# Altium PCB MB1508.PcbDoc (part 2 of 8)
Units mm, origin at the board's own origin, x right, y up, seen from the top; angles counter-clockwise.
Board outline 129 x 77 mm, 4 copper layers (Top Layer, GND, POWER, Bottom Layer), stack 1.582 mm thick; 399 components, 297 nets, 1407 pads, 1316 vias.
Unrouted connection lines stored in the file: 535.
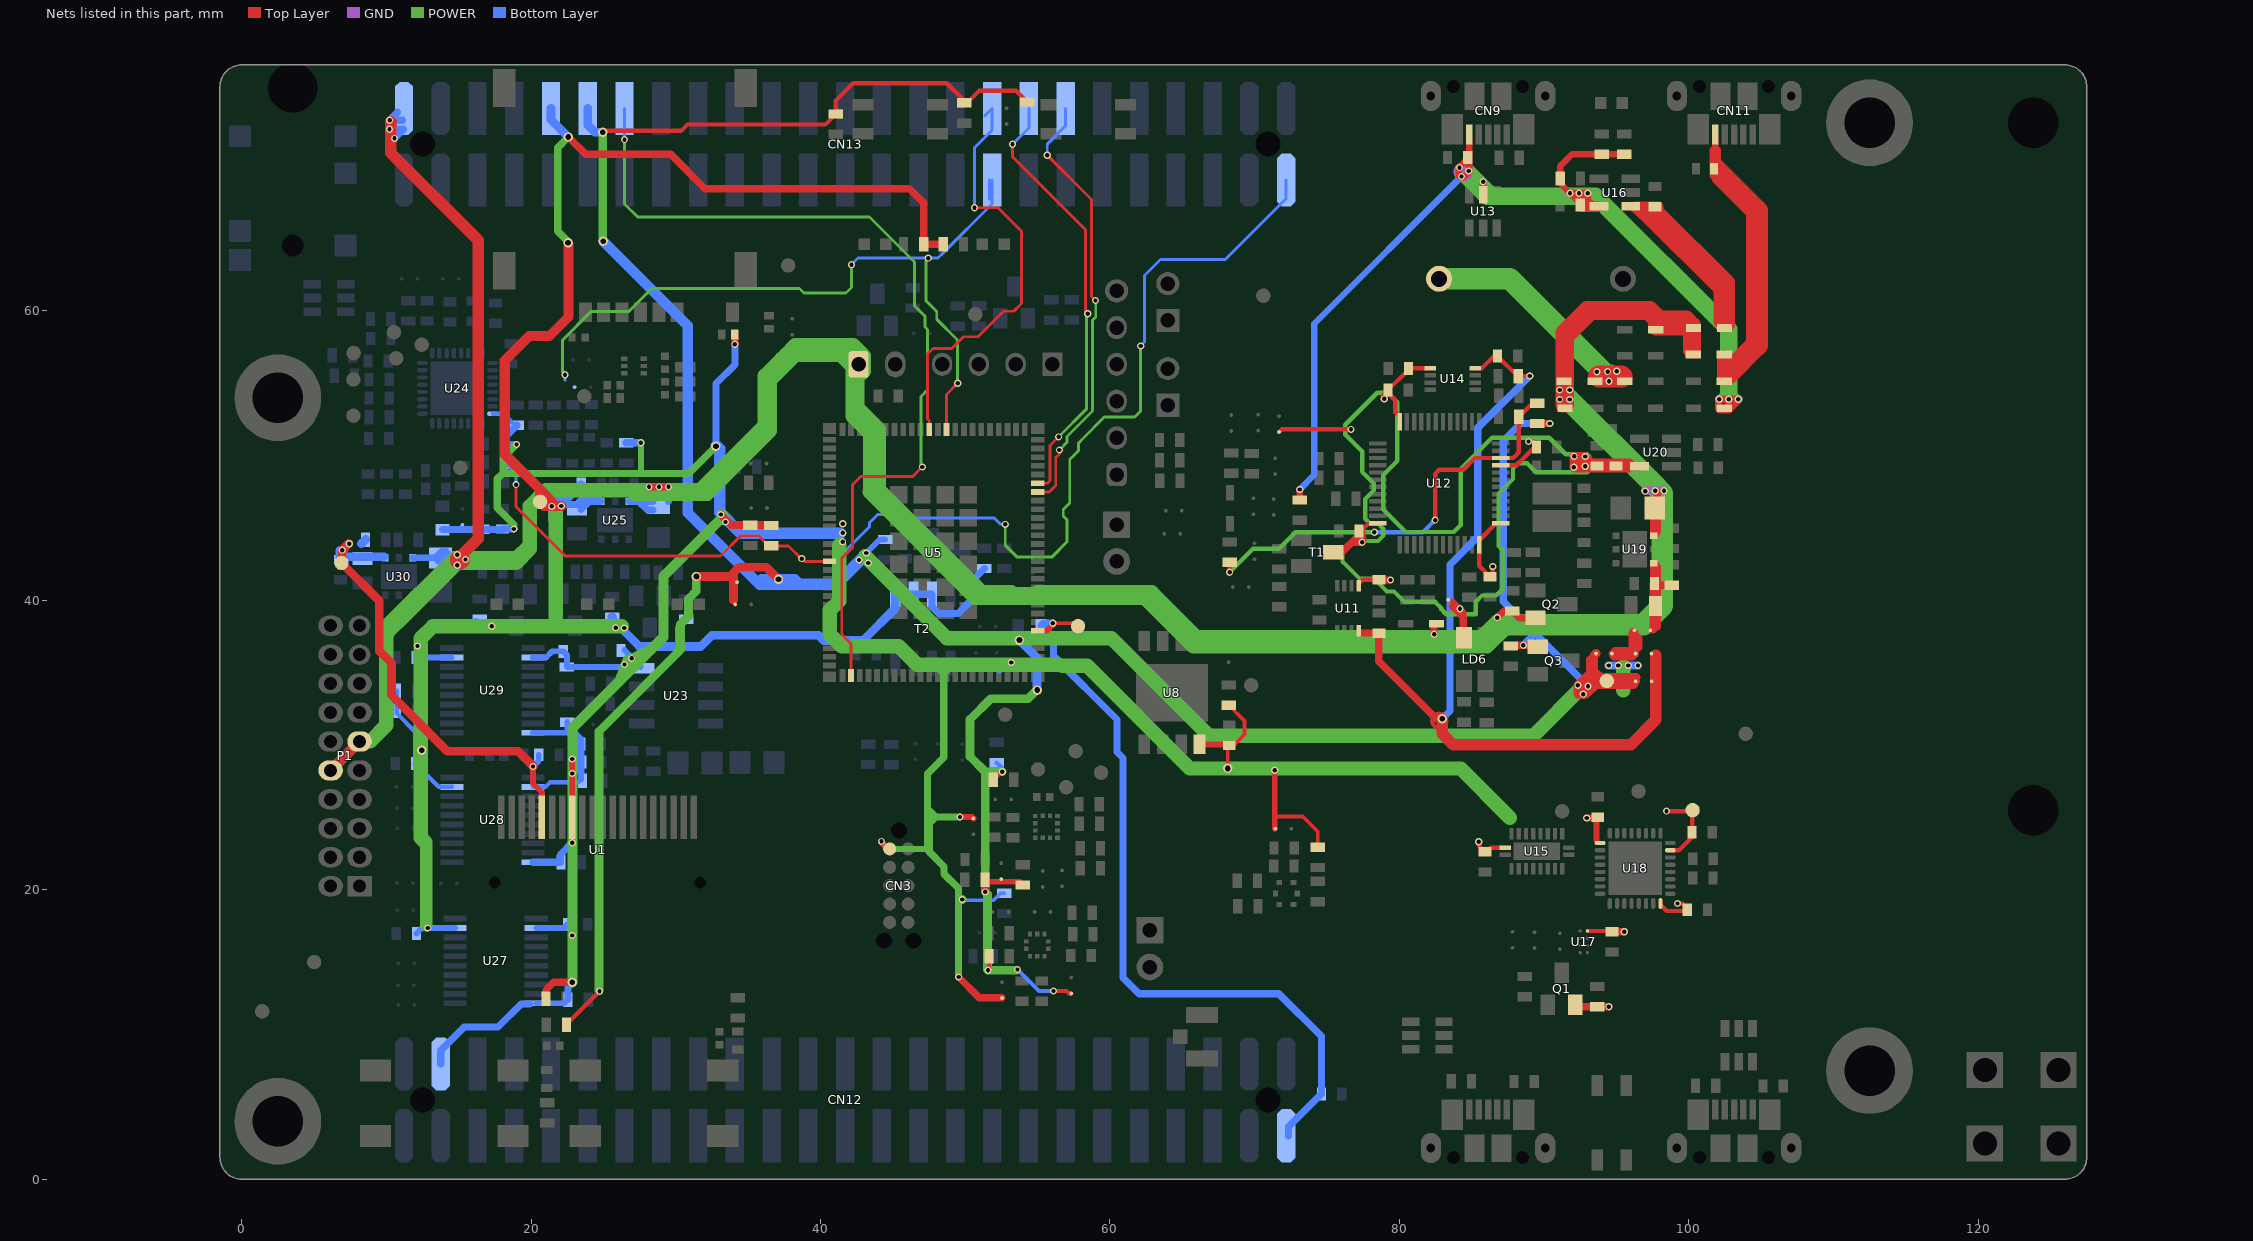
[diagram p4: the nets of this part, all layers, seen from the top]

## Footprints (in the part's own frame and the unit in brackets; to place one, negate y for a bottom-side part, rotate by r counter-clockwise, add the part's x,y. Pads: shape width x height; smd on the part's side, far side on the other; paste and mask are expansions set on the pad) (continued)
R0603 [mm]
  rect 0.64x1 smd mask+0.05: 1(-0.7,0) 2(0.7,0)
  silkscreen extent -1.05,-0.58 1.05,0.58, body extent -0.9,-0.5 0.9,0.5, height 0.56
REG_SOT23-5L [mm]
  rect 0.6x1.3 smd mask+0.05: 1(-0.95,-1.1) 2(0,-1.1) 3(0.95,-1.1) 4(0.95,1.1) 5(-0.95,1.1)
  silkscreen extent -1.6,-0.95 1.6,0.97, body extent -1.52,-1.25 1.52,1.25, height 1.1
SOLDER-BRIDGE_R0603-0R [mil]
  round 10 smd paste-393.7: 1(-19.68,0) 2(23.62,0)
  Top Layer region: -47.24,-19.69 -47.24,19.68 -15.75,19.68 3.94,0 -15.75,-19.69 -47.24,-19.69
  Top Layer region: -5.91,19.68 13.78,0 -5.91,-19.69 47.24,-19.69 47.24,19.68 -5.91,19.68
  silkscreen extent -50,-23 50,23, body extent -36,-20 36,20, height 22
STICKER_25X9 [mm] "Sticker 25mm x 9mm"
  silkscreen extent -12.5,-4.5 12.5,4.5
SWI_PANASONIC_EVQP2F02K [mm]
  rect 1.45x0.8 smd mask+0.05: 1(2.575,1) 2(2.575,-1) 3(-2.575,1) 4(-2.575,-1)
  silkscreen extent -2.4,-1.8 2.4,1.8, body extent -2.9,-1.8 2.9,1.8, height 2.7
SWI_WEALTHMETAL_TD-0341_4P_BLACK [mm]
  rect 1.52x2.16 smd mask+0.05: 1(-2.25,-4.75) 2(-2.25,4.75) 3(2.25,-4.75) 4(2.25,4.75)
  silkscreen extent -3,-3.5 3,3.5, body extent -3,-5.15 3,5.15, height 7.55
SWI_WEALTHMETAL_TD-0341_4P_BLUE [mm]
  rect 1.52x2.16 smd mask+0.05: 1(-2.25,-4.75) 2(-2.25,4.75) 3(2.25,-4.75) 4(2.25,4.75)
  silkscreen extent -3,-3.5 3,3.5, body extent -3,-5.15 3,5.15, height 7.55
TP_SMD_1MM [mm]
  round 1 smd paste-10 mask+0.05: 1(0,0)
  silkscreen extent -0.7,-0.7 0.7,0.7
预留天线 [mm]
  round 3.2 hole 3.5 unplated: 1(-6,34.5) 2(-6,-13)

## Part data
B1: library part MCD-00001, "Non-Open Push-Button 0.1A 24V BLACK", Manufacturer=WEALTHMETAL, Manufacturer_Part_Number=TD-0341
B2: library part MCD-00002, "Non-Open Push-Button 0.1A 24V", Manufacturer=WEALTHMETAL, Manufacturer_Part_Number=TD-0341
B3 B4 B5: library part MCD-00168, "EVQP2 - 4.7mm x 3.5 mm SMD Light Touch Switch", Manufacturer=PANASONIC, Manufacturer_Part_Number=EVQP2F02K
BT1: library part MCD-01623, "3xAAA ECONOMICAL PLASTIC BATTERY HOLDER", Manufacturer=KEYSTONE, Manufacturer_Part_Number=2479
C1 C6: library part MCD-00102, "Capacitor, MLCC, 100nF, 16V, X7R, 10%, 0402, T=0,5mm", Alternate_Manufacturer=MURATA, Alternate_Manufacturer_Part_Number=GCM155R71C104KA55D, Manufacturer=YAGEO, Manufacturer_Part_Number=CC0402KRX7R7BB104, Package=C0402
C2: library part MCD-00006, "Capacitor, MLCC, 100nF, 16V, X7R, 10%, 0402, T=0.5mm", Alternate_Manufacturer=MURATA, Alternate_Manufacturer_Part_Number=GCM155R71C104KA55D, Manufacturer=YAGEO, Manufacturer_Part_Number=CC0402KRX7R7BB104, Package=C0402
C3 C4 C5: library part MCD-00277, "Capacitor, MLCC, 33pF, 50V, NPO, 5%, 0402, T=0,5mm", Manufacturer=YAGEO, Manufacturer_Part_Number=CC0402JRNPO9BN330, Package=C0402
C7: library part MCD-01341, "Capacitor, MLCC, 10uF, 6V3, X5R, 20%, 0603, T=0,8mm"
C8 C10 C13 C14 C15 C16 C21 C22 C24 C29 C33 C42 C48 C49 C61 C64 C66 C68 C69 C72 C75 C87 C88 C89 C90: library part MCD-00237, "Capacitor, MLCC, 100nF, 6V3, X5R, 10%, 0603, T=0,8mm", Manufacturer=YAGEO, Manufacturer_Part_Number=CC0603KRX5R5BB104, Package=C0603
C9: library part MCD-00243, "Capacitor, MLCC, 10uF, 6V3, X5R, 10%, 0603, T=0,8mm", Manufacturer=YAGEO, Manufacturer_Part_Number=CC0603KRX5R5BB106, Package=C0603
C11 C46: library part MCD-00009, "Capacitor, MLCC, 4.7uF, 16V, X5R, 10%, 0603, T=0.8mm", Manufacturer=YAGEO, Manufacturer_Part_Number=CC0603KRX5R7BB475, Package=C0603
C12: library part MCD-00602, "Capacitor, MLCC, 220nF, 16V, 0402, X7R, 10%, T=0,5mm", Manufacturer=MURATA, Manufacturer_Part_Number=GRM155R71C223KA01J, Package=C0402
C17: library part MCD-00012, "Capacitor, MLCC, 2.2uF, 10V, X5R, 10%, 0603, T=0,8mm", Alternate_Manufacturer=KEMET, Alternate_Manufacturer_Part_Number=C0603C225K8PACTU, Manufacturer=YAGEO, Manufacturer_Part_Number=CC0603KRX5R6BB225, Package=C0603
C18: library part MCD-00638, "Capacitor, MLCC, 20pF, 50V, NPO, 5%, 0603, T=0,8mm", Manufacturer=YAGEO, Manufacturer_Part_Number=CC0603JRNPO9BN200, Package=C0603
C19 C20 C23 C25 C26 C28 C30 C31 C41 C43: library part MCD-00211, "Capacitor, MLCC, 100nF, 16V, X7R, 10%, 0603, T=0,8mm", Manufacturer=YAGEO, Manufacturer_Part_Number=CC0603KRX7R7BB104, Package=C0603
C27 C35: library part MCD-01006, "Capacitor, MLCC, 470nF, 16V, X7R, 10%, 0603, T=0.8mm", Manufacturer=YAGEO, Manufacturer_Part_Number=CC0603KRX7R7BB474, Package=C0603
C32 C45 C47 C50 C51 C57 C60 C62 C67 C73 C76 C77 C78 C79 C80 C81 C82: library part MCD-00238, "Capacitor, MLCC, 1uF, 6V3, X5R, 10%, 0603, T=0,8mm", Manufacturer=YAGEO, Manufacturer_Part_Number=CC0603KRX5R5BB105, Package=C0603
C34: library part MCD-00017, "Capacitor, MLCC, 10nF, 50V, X7R, 10%, 0603, T=0.8mm", Manufacturer=YAGEO, Manufacturer_Part_Number=CC0603KRX7R9BB103, Package=C0603
C36 C37 C56: library part MCD-00637, "Capacitor, MLCC, 10pF, 50V, NPO, 5%, 0603, T=0,8mm", Manufacturer=YAGEO, Manufacturer_Part_Number=CC0603JRNPO9BN100, Package=C0603
C38 C52 C55 C58 C84: library part MCD-00007, "Capacitor, Tantalum, 4.7uF, 16V, 10%, 4ohms, pkg Type_A (3216 metric), T=1.6mm", Manufacturer=AVX, Manufacturer_Part_Number=TAJA475K016R, Package=Type_A
C39 C70 C86: library part MCD-00014, "Capacitor, MLCC, 10uF, 25V, X5R, 10%, 0805, T=0,85mm", Manufacturer=YAGEO, Manufacturer_Part_Number=CC0805KRX5R8BB106, Package=C0805
C40 C44 C63 C74 C83 C85: library part MCD-00010, "Capacitor, MLCC, 1uF, 16V, X5R, 10%, 0603, T=0,8mm", Manufacturer=YAGEO, Manufacturer_Part_Number=CC0603KRX5R7BB105, Package=C0603
C53: library part MCD-00273, "Capacitor, MLCC, 1nF, 16V, X7R, 10%, 0603, T=0,8mm"
C54: library part MCD-01007, "Capacitor, MLCC, 10nF, 16V, X7R, 10%, 0603, T=0.8mm"
C59 C65: library part MCD-00238, "Capacitor, MLCC, 1uF, 6V3, X5R, 10%, 0603, T=0,8mm"
C71: library part MCD-00551, "Capacitor, MLCC, 2.2uF, 10V, X5R, 10%, 0603, T=0,8mm", Alternate_Manufacturer=YAGEO, Alternate_Manufacturer_Part_Number=CC0603KRX5R6BB225, Manufacturer=KEMET, Manufacturer_Part_Number=C0603C225K8PACTU, Package=C0603
CN1: library part MCD-01701, "RF Coxial Cable to uFL"
CN2: library part MCD-01699, "Socket_microsim 17.17*16.75, height 1.5mm, 6PIN"
CN3: library part MCD-00031, "Tag_Connector Header, 10x2, No legs", Manufacturer="TAG-CONNECT LLC", Manufacturer_Part_Number=TC2050-IDC-NL-FP
CN4: library part MCD-00313, "Header, 4x1, 2.54mm, VR, TH, Height 6mm/3mm", Alternate_Manufacturer=LIANYI, Alternate_Manufacturer_Part_Number=313104S1411160, Manufacturer=JIUBABA, Manufacturer_Part_Number=PHFS25-11-04-G0B115-T-1
CN5: library part MCD-00316, "Header, 6x1, 2.54mm, VR, TH, Height 6mm/3mm", Alternate_Manufacturer=LIANYI, Alternate_Manufacturer_Part_Number=313106S1411160, Manufacturer=JIUBABA, Manufacturer_Part_Number=PHFS25-11-06-G0B115-T-1
CN6: library part MCD-01583, "U.FL RF connector"
CN7: library part MCD-01581, "Header 2x1, 2.54mm, VR, TH, height 5.84mm/5.08 mm, height total 13.46 mm", Manufacturer=SAMTEC, Manufacturer_Part_Number=TSW-102-08-G-S
CN8 CN9 CN10 CN11: library part MCD-01698, "Micro-USB B Receptacle without Flange, Top Mount, Surface Mount, Lead-Free"
CN12 CN13: library part MCD-01931, "Header, 25x2, 2,54mm, VR, TH, Height 5.84mm/2.54mm, with alignment Pin"
CN14: library part MCD-01695, "Connector Jack socket Stereo 3.5mm, SMT", Manufacturer=TAIYI
D1 D2 D3 D4 D5 D6 D7 D8 D9 D10 D11 D12: library part MCD-00034, Manufacturer=STMICROELECTRONICS
H1 H2 H3 H4: library part MCD-00035, "POSITION HOLE C6D3R5"
HW8: library part MCD-00235, "Sticker to mention board reference + serial number", Manufacturer=n/a
HW9: library part MCD-00547, "Sticker to mention board CPN code", Manufacturer=n/a
JP1 JP2: library part MCD-00683, "Header, 2x1, 2,54mm, VR, TH, Height 5.84mm/2.54mm - Shunt Fitted by default", Alternate_Manufacturer=LIANYI, Alternate_Manufacturer_Part_Number=313102S111116, Manufacturer=SAMTEC, Manufacturer_Part_Number=TSW-102-07-x-S
JP3 JP4: library part MCD-00045, "Header, 2x1, 2,54mm, VR, TH, Height 5.84mm/2.54mm", Alternate_Manufacturer="JIUBABA; LIANYI", Alternate_Manufacturer_Part_Number=313102S111116;313102S111116, Manufacturer=SAMTEC, Manufacturer_Part_Number=TSW-102-07-x-S
L1: library part MCD-00047, "SMD Chip ferrite bead, 600R@100MHz +/-25%, 350mA, 500mohm DC, 0603, T=0.8mm", Manufacturer=TAI-TECH, Manufacturer_Part_Number=FCM1608KF-601T03
L2: library part MCD-01724, "Ferrite bead, 1000R @ 100MHz,  600mA, 350mOhm, 0603", Manufacturer=MURATA, Manufacturer_Part_Number=BLM18HE102SN1D
LD1 LD4 LD5: library part MCD-00320, "LED, Green, 0603", Manufacturer=EVERLIGHT, Manufacturer_Part_Number=19-213SY6C/S530-E2/TR8LED, Package="LED 0603"
LD2: library part MCD-00322, "LED, Red, 0603", Manufacturer=EVERLIGHT, Manufacturer_Part_Number=19-217/R6C-AL1M2VY/3T, Package="LED 0603"
LD3: library part MCD-00585, "LED Blue, 0603 SMD, Forward Voltage Min=2,8V, Max=3,8V", Alternate_Manufacturer=EVERLIGHT, Alternate_Manufacturer_Part_Number=19-217-BHC-ZL1M2RY-3T-V4, Manufacturer="OSRAM OPTO SEMICONDUCTORS", Manufacturer_Part_Number="LB Q39G-L2OO-35-1", Package="LED 0603"
LD6: library part MCD-00051, "LED Bicolor", Alternate_Manufacturer=EVERLUCK, Alternate_Manufacturer_Part_Number=LE-RGW35280, Manufacturer="AVAGO TECHNOLOGIES", Manufacturer_Part_Number=HSMF-A201-A00J1
LD7: library part MCD-00049, "LED, Red, 0603", Manufacturer=EVERLIGHT, Manufacturer_Part_Number=19-213-R6C-AP1Q2B/3T, Package="LED 0603"
P1: library part MCD-00309, "Socket 10x2, 2.00mm, RA, TH, Height 6.35mm/2.29mm", Alternate_Manufacturer=JIUBABA;CONNECT, Alternate_Manufacturer_Part_Number=FH200020C-12300;CNT-F200-2*10-GD-635/2.3, Manufacturer=SAMTEC, Manufacturer_Part_Number=SQT-110-01-F-D-RA
Q1 Q2: library part MCD-01494, "MOSFET, P-Channel , Vds: -20V, Id: -2.4A, Vgs(th): -1.5V, Vgs(max): +/-8V, Rdson:100mohm@Vgs=-1.8V", Alternate_Manufacturer="ON SEMICONDUCTOR", Alternate_Manufacturer_Part_Number=FDN304PZ, Manufacturer_Part_Number=FDN304P, Package=SOT23-3
Q3 Q6: library part MCD-01163, "MOSFET, N-Channel , Vds: 20V, Id: 2A, Vgs(th): 1.5V, Vgs(max): +/-8V, Rdson:120mohm@Vgs=1.8V, Qg=6.3nC", Manufacturer=FAIRCHILD, Manufacturer_Part_Number=FDN327N, Package=SOT-23-3
Q4 Q5 Q7 Q8 Q9 T1: library part MCD-00073, "NPN Bipolar Transistor", Alternate_Manufacturer="ON SEMICONDUCTOR", Alternate_Manufacturer_Part_Number="MMBT2222LT1G / MMBT2222ALT1G / MMBT2222ALT3G", Manufacturer_Part_Number=BSR14, Package=SOT23
R1 R3 R10 R11 R13 R18 R20 R21 R22 R30 R39 R40 R44 R53 R56 R60 R61 R65 R72 R74 R80 R82 R84 R97 R103 R105 R106 R122: library part MCD-00220, "Resistor,10K,0603,1%,1/10W", Manufacturer=YAGEO, Manufacturer_Part_Number=RC0603FR-0710KL, Package=R0603
R2 R37 R41 R42: library part MCD-00224, "Resistor,100R,0603,1%,1/10W", Manufacturer=YAGEO, Manufacturer_Part_Number=RC0603FR-07100RL, Package=R0603
R4 R8 R9: library part MCD-00285, "Resistor,15K,0402,5%,1/16W", Manufacturer=YAGEO, Manufacturer_Part_Number=RC0402JR-0715KL, Package=R0402
R5 R6 R7: library part MCD-00286, "Resistor,18R,0402,5%,1/16W", Manufacturer=YAGEO, Manufacturer_Part_Number=RC0402JR-0718RL, Package=R0402
R12 R75 R81 R83: library part MCD-00190, "Resistor,22R,0603,1%,1/10W", Manufacturer=YAGEO, Manufacturer_Part_Number=RC0603FR-0722RL, Package=R0603
R14 R16 R46 R48 R51 R54 R58 R59 R66 R67 R71 R73 R77 R79 R94 R107 R116: library part MCD-00223, "Resistor,100K,0603,1%,1/10W", Manufacturer=YAGEO, Manufacturer_Part_Number=RC0603FR-07100KL, Package=R0603
R15 R17 R88 R98 R118: library part MCD-00225, "Resistor,510R,0603,1%,1/10W", Manufacturer=YAGEO, Manufacturer_Part_Number=RC0603FR-07510RL, Package=R0603
R19 R23 R24 R25 R26 R27 R28 R35 R38 R45 R78 R87 R91 R93 R96 R99 R100 R110 R111 R123: library part MCD-00056, "Resistor,0R,0603,5%,1/10W", Manufacturer=YAGEO, Manufacturer_Part_Number=RC0603JR-070RL, Package=R0603
R29 R31 R32 R33 R34: library part MCD-00066, "Resistor,22R,0603,1%,1/10W", Manufacturer=YAGEO, Manufacturer_Part_Number=RC0603FR-0722RL, Package=R0603
R36: library part MCD-00221, "Resistor,36K,0603,1%,1/10W", Manufacturer=YAGEO, Manufacturer_Part_Number=RC0603FR-0736KL, Package=R0603
R43: library part MCD-00217, "Resistor,1K5,0603,1%,1/10W", Manufacturer=YAGEO, Manufacturer_Part_Number=RC0603FR-071K5L, Package=R0603
R47: library part MCD-00218, "Resistor,2K7,0603,1%,1/10W", Manufacturer=YAGEO, Manufacturer_Part_Number=RC0603FR-072K7L, Package=R0603
R49 R55 R62 R108 R109 R120 R121: library part MCD-00219, "Resistor,4K7,0603,1%,1/10W", Manufacturer=YAGEO, Manufacturer_Part_Number=RC0603FR-074K7L, Package=R0603
R50 R52: library part MCD-00197, "Resistor,330R,0603,1%,1/10W", Manufacturer=YAGEO, Manufacturer_Part_Number=RC0603FR-07330RL, Package=R0603
R57 R63 R70 R86 R89 R90 R101 R113: library part MCD-00222, "Resistor,47K,0603,1%,1/10W", Manufacturer=YAGEO, Manufacturer_Part_Number=RC0603FR-0747KL, Package=R0603
R64 R76: library part MCD-00070, "Resistor,1K,0603,1%,1/10W", Manufacturer=YAGEO, Manufacturer_Part_Number=RC0603FR-071KL, Package=R0603
R68: library part MCD-00478, "Resistor,43K,0603,1%,1/10W", Manufacturer=YAGEO, Manufacturer_Part_Number=RC0603FR-0743KL, Package=R0603
R69 R104 R119: library part MCD-01149, "Resistor,20K5,0603,1%,1/10W", Manufacturer=YAGEO, Manufacturer_Part_Number=RC0603FR-0720K5L, Package=R0603
R85 R102: library part MCD-00056, "Resistor,0R,0603,5%,1/10W"
R92: library part MCD-00506, "Resistor,620K,0603,1%,1/10W", Manufacturer=YAGEO, Manufacturer_Part_Number=RC0603FR-07620KL, Package=R0603
R95: library part MCD-00244, "Resistor,11K8,0603,1%,1/10W", Manufacturer=YAGEO, Manufacturer_Part_Number=RC0603FR-0711K8L, Package=R0603
R112 R114 R115: library part MCD-01723, "Resistor,2K15,0603,1%,1/10W", Manufacturer=YAGEO, Manufacturer_Part_Number=RC0603FR-072K15L, Package=R0603
R117: library part MCD-01155, "Resistor,10K2,0603,1%,1/10W", Manufacturer=YAGEO, Manufacturer_Part_Number=RC0603FR-0710K2L, Package=R0603
SB1 SB2 SB3 SB4 SB5 SB7 SB8 SB9 SB10 SB11 SB12 SB14 SB15 SB16 SB17 SB18 SB19 SB20 SB22 SB27 SB30 SB34 SB36 SB37 SB38 SB40 SB42 SB43 SB44 SB45 SB46 SB47 SB48 SB49 SB50 SB53 SB57 SB58 SB60 SB61: library part MCD-00071, "Solder Bridge ON", Manufacturer=YAGEO, Manufacturer_Part_Number=RC0603JR-070RL, Package=SB0603
SB6 SB13 SB21 SB23 SB24 SB25 SB26 SB28 SB29 SB31 SB32 SB33 SB35 SB39 SB41 SB51 SB52 SB54 SB55 SB56 SB59: library part MCD-00072, "Solder Bridge OFF", Manufacturer=YAGEO, Manufacturer_Part_Number=RC0603JR-070RL, Package=SB0603
T2: library part MCD-00572, "Power MOSFET - P-channel 30V - 0.045 OHM - 5A SO-8 - STripFET", Manufacturer=STMICROELECTRONICS
TP1 TP2 TP3 TP4 TP5 TP6 TP7 TP8 TP9 TP10 TP11 TP12 TP13 TP14 TP15 TP16 TP17 TP18 TP19 TP20 TP21 TP22 TP23 TP24 TP25: library part MCD-00074, "Test Point 1mm", Manufacturer=n/a
U1: library part MCD-01511, "128*64 20-pin OLED display driver SSD1306BZ Parallel or SPI interface", Manufacturer=RITDISPLAY, Manufacturer_Part_Number=9OL9935701000
U2 U4 U21: library part MCD-00251, "High power transient voltage suppressor, 7V breakdown", Manufacturer=STMICROELECTRONICS, Manufacturer_Part_Number=ESDA7P60-1U1M
U3: library part MCD-01696, "ESD protection", Manufacturer=WILLSEMI, Package=SOT-563
U5: library part MCD-01700, "NBIoT Module", Manufacturer=Murata, Manufacturer_Part_Number=TYPE-1SE
U6: library part MCD-01702, "High-performance MEMS nano pressure sensor:260-1260 hPa absolute digital output barometer", Manufacturer=STMICROELECTRONICS, Package=HLGA-10L
U7: library part MCD-00709, "3D accelerometer and 3D magnetometer", Manufacturer=STMICROELECTRONICS
U8: library part MCD-01749, "512Mb, 1.8V Multiple I/O Serial Flash Memory", Manufacturer=Micron, Package=W-PDFN-8
U9 U13 U22: library part MCD-00163, "Very low capacitance ESD protection", Manufacturer=STMICROELECTRONICS
U10: library part MCD-01447, "Capacitive digital sensor for relative humidity and temperature", Manufacturer=STMICROELECTRONICS, Package=HLGA-6L
U11 U14: library part MCD-00264, "Dual bit dual supply bus transceiver", Manufacturer="TEXAS INSTRUMENTS"
U12: library part MCD-00085, "Medium-density performance line ARM-based 32-bit MCU with 128KB Flash", Manufacturer=STMICROELECTRONICS
U15: library part MCD-01620, "Octal buffer/line driver with 5 V tolerant inputs/outputs; 3-state", Manufacturer=Nexperia, Manufacturer_Part_Number=74LVC541ABQ,115, Package=DHVQFN20
U16: library part MCD-00083, "Enhanced single channel power switches with active low enable pin", Alternate_Manufacturer="TEXAS INSTRUMENTS", Alternate_Manufacturer_Part_Number=TPS2041C, Manufacturer=STMICROELECTRONICS
U17: library part MCD-01624, "Dual-Channel 10-Ω SPST Analog Switch", Manufacturer="TEXAS INSTRUMENTS", Package=DSBGA
U18: library part MCD-01622, "USB-Serial Dual Channel (UART/I2C/SPI) Bridge"
U19 U25 U30: library part MCD-00581, "LDO Linear Voltage Regulator IC Positive Adjustable 1 Output Adjustable 1.3A 6-DFN (3x3)", Manufacturer=STMICROELECTRONICS, Package="DFN6 (3x3)"
U20: library part MCD-00086, "Ultra low drop-low noise BiCMOS voltage, regulators low ESR capacitors compatible", Manufacturer=STMICROELECTRONICS
U23: library part MCD-00293, "I2C memory", Manufacturer=STMICROELECTRONICS
U24: library part MCD-01621, "Ultra-Low Power Stereo Audio Codec"
U26: library part MCD-00247, "Quad Bidir ESD protection", Manufacturer=STMICROELECTRONICS
U27 U28 U29: library part MCD-00289, "8bits_bidirectionnal level shifter, Delay 312ns/1V8", Manufacturer="TEXAS INSTRUMENTS"
X1: library part MCD-00092, "Crystal 8MHz, 8pF, +-20ppm, 500ohms max,  SMD", Manufacturer=NDK, Manufacturer_Part_Number="NX3225GD 8MHz EXS00A-CG04874"
X2: library part MCD-01836, "Oscillator 26Mhz, +-2ppm, Vcc:1.8V typ (1.7V min), square wave: [0.1Vcc;0.9Vcc]", Manufacturer=TXC, Package="2016 size"

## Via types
v1: diameter 0.5, hole 0.3, Top Layer to Bottom Layer, tented both sides, 1301 vias
v2: diameter 0.65, hole 0.4, Top Layer to Bottom Layer, tented both sides, 14 vias
v3: diameter 0.5/0.5/0.5/0.5 (per signal layer), hole 0.3, Top Layer to Bottom Layer, tented both sides, 1 vias

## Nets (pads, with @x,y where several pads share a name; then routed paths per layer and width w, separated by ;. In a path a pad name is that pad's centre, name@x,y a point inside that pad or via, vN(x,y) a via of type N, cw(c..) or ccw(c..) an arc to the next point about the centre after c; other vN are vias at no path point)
1V8: C15.2 C27.1 C33.2 C35.1 C45.1 C46.1 C59.1 C61.1 C63.1 C64.1 C68.1 C69.1 C72.2 C73.1 CN3.1 CN12.48 L2.2 Q1.2 R3.1 R8.2 R10.2 R13.2 R40.1 R44.2 R65.1 R72.2 R85.2 R89.2 R103.1 R105.1 R106.1 R108.1 R109.1 SB7.2 SB12.2 SB27.1 SB33.2 SB34.2 SB36.2 SB39.2 SB51.1 TP24.1 U1.8 U8.8 U15.20 U17.A2 U18.1 U18.16 U18.23 U23.8 U24.32 U27.2 U27.10 U28.2 U28.10 U29.2 U29.10 | length 299.6
  Top Layer w0.254: v2(68.143,28.382) 68.143,29.868 C15.2@68.25,29.976 ; R40.1@68.212,32.753 69.298,31.667 69.298,30.72 C15.2@68.554,29.976 ; SB27.1@71.387,24.272 SB27.1@71.437,24.222 ; 71.387,25.06 73.33,25.06 74.358,24.033 R44.2@74.358,22.93 ; U17.A2@92.999,17.15 C35.1@94.401,17.15 ; U18.1@93.663,23.277 93.544,23.395 93.544,24.854 93.676,24.723 93.718,24.681 93.718,23.229 U18.1@93.872,23.229
  Top Layer w0.3: v1@85.497,23.318 v1(85.486,23.318) 85.486,23.067 C27.1@85.929,22.624 ; C27.1@86.114,22.702 86.32,22.908 U15.20@87.306,22.908 ; U18.16@98.047,19.054 98.047,18.96 98.48,18.527 99.696,18.527 99.897,18.728 99.572,19.053 v1(99.219,19.053) ; v1(98.459,25.433) 99.987,25.433 100.239,25.182 C46.1@100.239,24.049 ; U18.23@98.722,22.729 99.318,22.729 100.237,23.648 100.237,24.475
  Top Layer w0.4: v1(22.85,23.241) U1.8@22.85,24.999 v1(22.85,28.037) v1(22.85,29.038) ; v1(44.218,23.341) 44.218,23.266 44.66,22.824 CN3.1@44.781,22.824 ; v1(49.644,25.031) 50.464,25.031 SB7.2@50.563,24.932 ; U8.8@66.191,30.039 68.187,30.039 C15.2@68.25,29.976 ; SB27.1@71.387,24.222 71.387,24.272 71.387,25.06 v1(71.387,28.26)
  Top Layer w0.5: R3.1@21.025,12.476 21.025,13.081 21.554,13.61 v2(22.842,13.61) ; R8.2@34.082,58.358 34.085,58.354 v1(34.085,57.697) ; v1(49.543,13.971) 50.978,12.536 SB12.2@52.546,12.536 ; Q1.2@92.158,12.062 92.31,11.91 R65.1@93.68,11.91 v1(94.48,11.91) ; v1(92.947,24.957) C33.2@93.647,24.957 ; C33.2@93.544,24.854 C33.2@93.647,24.957 ; C33.2@93.709,25.018 C33.2@93.647,24.957 ; SB33.2@94.692,36.32 96.274,36.32 SB36.2@96.325,36.269 ; C35.1@94.701,17.1 94.705,17.104 v1(95.538,17.104)
  Top Layer w0.55: v1(33.111,45.929) 33.79,45.251 33.799,45.251 33.855,45.194 R13.2@36.603,45.194
  Top Layer w0.7: 94.873,36.182 96.076,36.182 ; 94.949,36.408 96.152,36.408 ; 96.192,36.539 96.192,37.742 ; 96.447,36.774 96.447,37.374
  POWER w0.254: v1@49.966,19.325 ccw(c49.787,19.325) v1@49.966,19.325
  POWER w0.4: 27.589,48.817 v1(27.589,50.892) ; v1(44.218,23.341) 44.218,23.266 44.66,22.824 47.388,22.824
  POWER w0.5: v1(18.813,44.926) 18.813,45.225 17.665,46.373 17.665,48.399 18.072,48.806 ; v1(18.99,50.764) 18.072,49.846 18.072,48.806 ; 27.589,48.817 27.641,48.764 ; v2(32.774,50.651) 30.887,48.764 27.641,48.764 ; 33.111,45.421 v1(33.111,45.929) 33.111,46.019 33.242,46.019 33.434,45.828 v1(33.434,45.411) ; 48.037,35.432 48.525,34.944 ; 49.013,35.432 48.525,34.944 ; v1(49.543,13.971) 49.543,20.094 48.526,21.112 48.526,21.608 47.517,22.617 ; v1(49.644,25.031) 47.971,25.031 ; 18.072,48.806 18.115,48.764 27.641,48.764 ; 47.388,25.614 47.971,25.031 ; 47.388,25.614 47.388,22.824 47.388,22.745 47.517,22.617 ; 47.388,25.614 47.388,28.008 48.525,29.145 48.525,34.944 ; 47.517,22.617 47.517,24.576 47.971,25.031
  POWER w0.7: v2@22.85,13.61 v1(22.85,16.836) v1(22.85,28.037) v1(22.85,29.038) 22.85,31.155 29.14,37.445 29.14,41.643 33.045,45.548 ; 26.172,34.565 26.542,35.533 26.668,35.863 v1(26.946,35.987) ; v1@26.99,36.006 v1(26.946,35.987) ; 28.177,36.536 v1(26.946,35.987)
  POWER w1: 41.29,43.814 41.29,39.953 40.639,39.302 40.639,37.662 41.481,36.819 45.405,36.819 46.676,35.549 56.513,35.549 ; 56.701,35.472 58.429,35.472 65.522,28.379 71.387,28.379 84.238,28.379 87.634,24.984 ; 95.482,33.792 95.482,35.445
  Bottom Layer w0.2: 32.668,50.966 32.499,50.797 32.499,50.437 32.752,50.184 ; 32.861,51.039 33.345,50.555 33.345,50.35
  Bottom Layer w0.254: v1(49.787,19.325) 49.837,19.275 51.951,19.275 52.44,19.764 R72.2@52.709,19.764
  Bottom Layer w0.3: U24.32@17.338,52.9 18.08,52.9 R89.2@18.886,52.095 ; U28.2@20.131,27.107 20.999,27.107 21.312,27.421 23.262,27.421 R103.1@23.458,27.617
  Bottom Layer w0.4: U29.10@20.121,30.848 22.671,30.848 ; U29.2@20.121,36.048 21.037,36.048 21.463,36.474 C69.1@22.23,36.474 22.473,36.231 R109.1@22.473,35.396 U23.8@27.564,35.396 ; U27.10@20.353,12.154 22.292,12.154 R105.1@22.547,12.409 ; U27.2@20.353,17.354 22.26,17.354 C68.1@22.522,17.616 22.522,17.512 22.85,17.184 v1(22.85,16.836) ; R108.1@22.498,31.583 22.498,31.02 22.671,30.848 ; v1(22.85,28.037) 23.454,28.641 C63.1@23.454,28.687 ; 22.946,30.848 22.671,30.848 ; R103.1@23.458,27.617 23.458,28.037 ; C63.1@23.505,28.692 C63.1@23.505,28.82 ; C61.1@26.456,36.565 U23.8@27.585,35.436
  Bottom Layer w0.5: CN12.48@13.76,7.955 13.76,8.884 15.386,10.509 17.719,10.509 19.316,12.107 U27.10@19.912,12.107 ; L2.2@13.884,44.891 17.982,44.891 C72.2@18.017,44.926 v1(18.813,44.926) ; v1(18.99,50.764) 18.216,50.764 C59.1@18.18,50.8 18.18,51.266 R89.2@19.019,52.105 ; U28.10@20.131,21.907 22.04,21.907 22.04,22.431 v1(22.85,23.241) ; R105.1@22.547,12.409 22.547,13.316 v2(22.842,13.61) ; 22.704,31.129 22.828,31.005 23.454,30.379 C64.1@23.454,30.065 C64.1@23.454,29.642 ; v1(22.85,29.038) C64.1@23.454,29.642 ; C63.1@23.454,28.641 23.454,28.041 23.458,28.037 ; C63.1@23.454,28.687 C64.1@23.454,29.642 ; R85.2@26.579,50.892 v1(27.589,50.892) ; v2(32.774,50.651) 32.774,54.976 34.085,56.287 v1(34.085,57.697) ; 52.369,35.184 52.369,35.292 52.778,35.702 v1(53.186,35.702)
  Bottom Layer w0.55: v1@94.466,35.504 v1@96.497,35.504
  Bottom Layer w0.8: 33.041,50.384 33.041,46.075 34.469,44.646 v1@41.361,44.646
  other v1: 94.466,35.494 95.128,35.494 95.812,35.494 96.497,35.494 26.456,35.566 41.528,44.053 41.536,44.659 41.536,45.285
1V8_CS: C21.1 C29.1 R54.2 SB35.1 SB36.1 U11.8 U14.8 | length 64.1
  Top Layer w0.254: 82.757,31.176 cw(c82.76,31.676) 82.376,31.996 cw(c82.76,31.676) 83.104,31.313
  Top Layer w0.3: U14.8@85.251,56.046 85.716,56.046 86.54,56.871 C29.1@86.785,56.871 88.157,55.499 R54.2@88.211,55.499 v1(89.007,55.499)
  Top Layer w0.5: 77.364,37.736 78.573,37.736 C21.1@78.585,37.724 78.585,35.788 82.376,31.996 82.555,31.817 v2(82.961,31.817)
  Top Layer w0.8: v2(82.961,31.817) 82.961,30.775 83.731,30.005 95.997,30.005 97.729,31.738 97.729,36.206
  Bottom Layer w0.5: v2(82.961,31.817) 83.495,32.351 83.495,42.453 85.426,44.384 85.426,51.918 v1(89.007,55.499)
1V8_LDO: C39.1 C42.2 R69.2 SB34.1 U19.4 | length 10.3
  Top Layer w0.5: 97.482,37.974 97.553,38.045 ; 97.553,37.974 97.553,38.045 ; C42.2@97.553,41.169 C42.2@97.553,41.069 ; C42.2@97.573,41.304 U19.4@97.573,42.488 ; 97.667,38.159 97.553,38.045 ; U19.4@97.68,42.485 97.822,42.343 C42.2@97.822,41.05 ; 97.822,38.156 C42.2@97.822,41.05 ; R69.2@98.835,41.05 C42.2@97.822,41.05 ; 97.553,38.045 C42.2@97.553,41.069 ; C42.2@97.553,41.069 97.573,41.05 C42.2@97.822,41.05
1V8_MD: CN13.40 Q3.1 R1.2 R14.1 R16.2 R18.1 R20.1 R21.1 R22.1 R58.2 R62.1 R74.2 R82.2 R122.2 SB1.1 SB4.2 SB11.2 SB16.2 SB33.1 SB35.2 TP22.1 | length 269.2
  Top Layer w0.3: R1.2@22.441,10.668 22.441,10.7 v1(24.733,12.991) ; v2@24.951,72.44 30.363,72.44 30.803,72.88 40.338,72.88 R14.1@41.066,73.608 41.066,74.545 42.253,75.732 48.73,75.732 49.945,74.517 R122.2@49.945,74.375 50.118,74.375 50.948,75.205 53.522,75.205 54.278,74.449 R16.2@54.278,74.443 ; v1@51.646,14.442 R20.1@51.646,15.414 ; R21.1@51.947,27.59 52.511,28.154 v1(52.555,28.154) ; v1(56.102,12.998) 57.003,12.998 57.169,12.832 SB16.2@57.319,12.832
  Top Layer w0.4: R18.1@51.385,20.688 51.524,20.549 R22.1@53.811,20.549
  Top Layer w0.5: v2@36.935,41.616 v2(37.098,41.453) ; R18.1@51.372,20.701 51.385,20.688 v1(51.385,19.852) ; R58.2@87.788,36.899 v1(88.572,36.899) 89.45,36.899 Q3.1@89.566,36.783 ; R62.1@89.539,52.225 89.541,52.223 v1(90.387,52.223)
  Top Layer w0.6: v2(31.424,41.643) 33.845,41.643 ; 33.989,40.008 33.989,41.905 34.375,42.291 36.26,42.291 v2@36.935,41.616 ; 92.349,33.499 92.893,33.499 93.567,34.173 ; 93.186,35.891 93.186,34.98 ; 93.263,35.056 93.186,34.98 ; 93.436,34.617 93.223,34.403 ; 93.544,35.016 93.775,34.786 ; 93.577,34.678 96.366,34.678 ; SB33.1@93.592,36.32 93.442,36.17 93.442,34.505 93.544,34.403 ; 93.748,34.355 93.567,34.173 ; 96.188,34.173 93.567,34.173 ; SB35.2@96.333,34.403 93.544,34.403 ; 93.186,34.403 93.205,34.385 ; 93.186,34.403 93.223,34.403 ; 93.186,34.403 93.186,34.98 ; 93.186,34.98 v1(92.338,34.131) 92.338,33.518 93.205,34.385 ; 93.205,34.385 93.417,34.173 93.567,34.173 ; 93.205,34.385 93.223,34.403 ; 93.223,34.403 93.544,34.403
  POWER w0.6: v1@24.688,13.036 24.688,30.936 30.329,36.577 30.329,38.349 30.875,38.894 30.875,40.091 31.424,40.64 v2(31.424,41.643) ; v2(24.951,72.35) 24.951,64.853 v2(24.994,64.81) ; v1(52.555,28.154) 51.385,28.154 ; v1@53.564,14.442 53.563,14.443 v1(51.574,14.443) 51.547,14.47 51.547,19.69 v1(51.385,19.852) 51.385,28.154 ; v2(54.983,33.798) 54.941,33.798 54.338,33.195 51.767,33.195 50.331,31.759 50.331,29.208 51.385,28.154
  POWER w1: v1@43.095,43.034 48.735,37.393 60.098,37.393 66.846,30.645 89.27,30.645 92.615,33.991
  Bottom Layer w0.3: R74.2@52.165,28.784 52.555,28.395 v1(52.555,28.154) ; v1(53.613,14.49) 55.104,12.998 v1(56.102,12.998)
  Bottom Layer w0.4: v1(43.167,43.267) 44.099,44.199 R82.2@44.462,44.199
  Bottom Layer w0.5: 35.76,41.114 35.796,41.114 ; v1(88.572,36.899) 89.366,37.694 ; v1(90.387,52.223) 88.392,52.223 87.179,51.01 87.179,39.924 92.655,34.448 v1(92.338,34.131)
  Bottom Layer w0.6: CN13.40@23.92,73.995 23.92,72.85 24.42,72.35 v2(24.951,72.35) ; v2(53.745,37.25) 54.962,36.032 v2@54.962,33.946
  Bottom Layer w0.7: v2(24.994,64.81) 30.825,58.979 30.825,46.049 35.622,41.252 35.935,41.252 ; 35.923,41.458 v2(37.098,41.453) 38.225,41.453 38.564,41.114
  Bottom Layer w0.8: 35.796,41.114 38.564,41.114 41.106,41.114 v1@43.133,43.141 ; v1@92.939,33.882 ccw(c92.689,33.882) v1@92.939,33.882
  other v1: 92.712,33.518 93.035,34.062 43.297,42.581 42.657,42.784
3V3: C70.1 C75.2 C87.2 C88.2 C89.2 CN13.42 R15.2 R17.2 R76.2 R88.2 R98.2 R104.2 R118.2 R120.1 R121.1 SB41.2 T2.1 T2.2 T2.3 TP9.1 U25.4 U27.19 U28.19 U29.19 | length 176.9
  Top Layer w0.254: TP9.1@20.628,46.822 20.927,46.522 20.958,46.491 v1(21.427,46.491)
  Top Layer w0.5: v2(22.574,72.02) 23.77,70.824 29.647,70.824 32.024,68.447 46.15,68.447 47.129,67.468 R15.2@47.129,64.608 R17.2@48.483,64.608
  Top Layer w0.7: 21.622,46.659 20.628,47.653 ; v1(22.081,46.522) 20.927,46.522 20.898,46.522 20.628,46.792 20.628,46.822 20.628,47.653 ; v2@22.585,64.597 22.585,59.579 21.27,58.264 19.865,58.264 18.177,56.577 18.177,50.103 20.628,47.653
  POWER w0.5: v2@12.349,29.637 12.351,29.963 12.352,30.185 ; 12.377,23.854 12.385,23.846 12.575,23.656 ; 12.539,23.838 12.648,23.729 12.575,23.656 ; 12.563,17.544 12.754,17.354 v1(12.851,17.354) 12.945,17.447 12.934,17.447 12.934,17.628 ; 12.563,21.188 12.575,21.199 ; 12.575,17.63 12.575,21.199 ; 12.684,17.878 12.934,17.628 ; 12.934,21.757 12.934,21.559 ; v2(22.56,64.71) 22.56,64.773 21.836,65.497 21.836,71.282 v2(22.574,72.02) ; 12.575,21.199 12.934,21.559 ; 12.575,21.199 12.575,23.395 12.575,23.656 ; 12.575,23.656 12.936,23.295 12.936,21.561 12.934,21.559 ; 12.934,17.628 12.934,21.559
  POWER w1: 12.684,23.285 12.575,23.395 12.385,23.585 12.385,23.846 12.385,37.382 13.219,38.216 21.467,38.216 21.473,38.223 v1@26.253,38.223 ; 21.713,38.464 21.713,46.185
  Bottom Layer w0.3: R120.1@10.707,33.761 10.707,32.206 12.022,30.891 C89.2@12.022,28.727 ; C89.2@12.182,28.541 13.616,27.107 U28.19@14.531,27.107
  Bottom Layer w0.4: C89.2@12.022,28.727 12.539,29.244 v2@12.539,29.637 ; C88.2@12.073,36.042 12.131,36.1 12.156,36.126 12.233,36.202 C88.2@12.156,36.278 ; C87.2@12.074,16.981 12.447,17.354 v1(12.851,17.354) U27.19@14.753,17.354 ; C88.2@12.376,36.048 U29.19@14.521,36.048 ; R118.2@16.192,38.589 16.57,38.211 v1(17.287,38.211) ; 30.129,36.813 30.129,38.101 R88.2@30.727,38.699
  Bottom Layer w0.5: C88.2@12.131,36.042 C88.2@12.131,36.1 ; C88.2@12.156,36.1 12.156,36.126 12.156,36.278 v1(12.156,36.839) ; 21.713,46.621 23.177,46.621 23.397,46.84 ; C70.1@23.453,46.273 24.021,46.84 ; 24.106,46.925 24.021,46.84 ; T2.1@45.164,40.415 T2.2@46.434,40.415 T2.3@47.704,40.415 47.704,39.553 48.167,39.09 49.511,39.09 50.349,39.928 ; SB41.2@50.769,40.263 50.741,40.291 50.741,41.607 R76.2@51.325,42.192 ; 24.021,46.84 23.411,46.84 23.586,47.015 24.604,47.015 24.779,46.84 24.021,46.84
  Bottom Layer w0.6: CN13.42@21.38,73.995 21.38,73.213 v2(22.574,72.02) ; 21.402,47.008 22.459,47.008 23.444,47.993 R104.2@23.471,47.993 ; R98.2@25.596,38.851 25.596,38.711 27.495,36.813 30.129,36.813 31.727,36.813 32.501,37.587 39.866,37.587 40.235,37.219 42.93,37.219 45.164,39.453 T2.1@45.164,40.415
  Bottom Layer w0.7: v1(21.427,46.491) 21.427,46.982
  other v1: 26.436,38.087 25.84,38.104
  other v2: 12.441,29.637
3V3_STLK: C19.2 C22.2 C23.2 C24.2 C28.2 C31.2 C43.2 C44.2 LD6.4 SB25.2 SB29.1 T1.3 U11.1 U12.1 U12.9 U12.24 U12.36 U12.48 U14.1 U20.5 | length 123.2
  Top Layer w0.2: U11.1@77.199,41.001 U11.1@77.199,41.178 ; C23.2@79.224,54.331 79.224,54.381 C23.2@79.224,54.537 ; C24.2@80.52,55.832 C24.2@80.624,55.832
  Top Layer w0.254: C19.2@77.215,44.793 77.361,44.793 77.906,45.338 U12.36@78.519,45.338 ; C19.2@77.374,44.517 77.425,44.466 77.59,44.302 v1@77.59,44.007 ; C24.2@80.624,55.832 C24.2@80.624,55.91 ; v1(88.924,50.974) 89.31,50.974 C31.2@89.599,50.685
  Top Layer w0.3: SB25.2@71.689,51.63 71.689,51.634 71.867,51.812 v1(76.656,51.812) ; U11.1@77.199,41.178 77.435,41.414 v1@79.308,41.414 ; C23.2@79.224,54.331 79.724,53.831 79.724,53.004 80.019,52.709 U12.24@80.019,52.338 ; C23.2@79.224,54.537 C24.2@80.52,55.832 ; C24.2@80.838,56.046 U14.1@82.151,56.046 ; v1(86.46,42.338) 86.46,41.823 C28.2@86.267,41.63 85.519,42.378 U12.48@85.519,43.838 85.519,44.154 86.703,45.338 U12.1@87.019,45.338 ; U12.9@87.019,49.338 88.103,49.338 C31.2@89.45,50.685
  Top Layer w0.4: C24.2@80.624,55.832 C24.2@80.838,56.046 ; 83.697,39.911 v1@84.176,39.432 ; v1(84.195,39.417) 84.458,39.154 84.458,38.782
  Top Layer w0.5: T1.3@75.43,43.321 76.019,43.321 77.215,44.517 C19.2@77.215,44.793 ; 76.752,44.007 v1(77.425,44.007) 77.425,44.466 C19.2@77.425,44.68 ; C22.2@78.585,41.414 78.596,41.403 v1(79.395,41.403) ; v1(78.962,53.92) 78.962,54.119 C23.2@79.224,54.381 ; 83.649,39.612 84.411,38.85 LD6.4@84.411,37.189
  Top Layer w0.6: v1@92.064,49.963 v1(92.064,49.202) 92.137,49.129 93.664,49.129 95.837,49.129 ; 92.53,49.51 v1(92.077,49.963) v1@92.717,49.963 ; v1(92.839,49.938) 93.292,49.485 93.664,49.485 95.911,49.485 U20.5@96.129,49.267 ; C43.2@93.241,49.267 U20.5@96.129,49.267 ; U20.5@96.603,49.267 U20.5@96.129,49.267
  POWER w0.3: 76.075,42.676 77.246,41.505 78.248,41.505 79.141,40.613 79.63,40.613 80.352,39.89 82.472,39.89 82.889,39.473 82.889,39.395 83.246,39.038 85.283,39.038 85.283,39.899 85.712,40.329 86.698,40.329 87.141,40.772 87.141,43.466 86.853,43.755 86.853,47.375 87.858,48.38 87.858,49.115 88.205,49.463 88.842,49.463 89.449,48.856 92.979,48.856 93.122,48.999 93.122,49.946 92.974,50.094 91.501,50.094 90.364,51.231 86.404,51.231 84.241,49.068 84.241,45.198 83.766,44.723 80.44,44.723 78.877,46.286 78.877,48.649 79.867,49.639 79.867,53.688 79.218,54.337 78.469,54.337 76.266,52.134 76.266,51.455 77.425,50.296 77.425,48.882 78.222,48.086 78.222,47.589 77.638,47.005 77.638,45.641 77.979,45.299 78.525,45.299 78.877,44.948 78.877,44.451 78.525,44.099 76.797,44.099 76.075,43.378 76.075,42.676
  other v1: 92.851,49.267
3V6: C74.2 C86.1 C90.2 R119.2 TP6.1 U1.5 U30.4 | length 32.8
  Top Layer w0.4: v1(20.132,28.518) 20.132,27.334 20.75,26.716 U1.5@20.75,24.999
  Top Layer w0.6: TP6.1@6.899,42.581 9.515,39.965 9.515,36.5 10.35,35.664 10.35,33.436 14.211,29.575 19.104,29.575 20.145,28.534 20.132,28.521 v1(20.132,28.518) ; TP6.1@6.949,42.859 v1(6.949,43.47) v1@7.381,43.902
  GND w0.6: v1(6.949,43.47) v1@7.381,43.902
  Bottom Layer w0.4: v1(20.132,28.518) 20.139,28.518 20.526,28.905 C74.2@20.526,29.328
  Bottom Layer w0.6: C90.2@6.802,42.923 v1@6.802,43.47 ; C90.2@6.994,43.011 U30.4@9.85,43.011 ; R119.2@8.268,43.902 R119.2@8.565,44.199
  other v1: 7.432,43.902
5V: C38.1 C58.1 C84.1 CN13.50 D2.1 D3.2 D4.2 D5.2 D6.2 D12.2 JP1.1 P1.6 P1.15 Q2.2 R59.2 U19.6 U25.6 U30.6 | length 366.7
  Top Layer w0.254: D5.2@97.319,58.875 97.319,59.452
  Top Layer w0.5: v1(28.146,47.838) v1(28.843,47.838) v1(29.493,47.838) ; v1(82.402,37.657) 82.402,38.212 D2.1@82.572,38.382 ; v1(86.774,38.807) 87.233,39.266 R59.2@87.806,39.266 88.292,38.78 Q2.2@89.406,38.78 ; U19.6@97.573,44.545 C38.1@97.573,46.618 ; v1(97.678,47.574) 97.822,47.43 97.822,44.715 U19.6@97.68,44.572
  Top Layer w0.7: P1.15@6.15,28.246 P1.6@8.15,30.246
  Top Layer w0.75: 15.158,43.08 cw(c15.071,42.793) 15.371,42.793 cw(c15.071,42.793) 15.158,43.08
  Top Layer w0.8: v1@10.326,73.068 10.31,73.052 10.31,70.916 16.352,64.874 16.352,44.274 15.158,43.08 15.137,43.058
  Top Layer w1: D6.2@91.282,53.485 91.282,58.52 92.945,60.183 96.845,60.183 ; D6.2@91.562,53.49 91.562,58.525 ; 91.714,58.324 93.263,59.874 ; 93.086,59.874 93.263,59.874 ; 93.377,59.988 93.263,59.874 ; 96.985,59.874 93.263,59.874 ; 97.558,59.515 98.016,59.515 ; D5.2@97.728,58.79 D3.2@100.096,58.79 ; D5.2@98.125,58.904 96.845,60.183 ; 98.581,58.95 98.016,59.515 ; 100.096,57.257 D3.2@100.096,58.79 ; D3.2@100.096,58.815 D3.2@100.096,58.79 ; D12.2@100.331,57.207 100.331,58.764 100.306,58.79 D3.2@100.096,58.79 ; D3.2@100.331,58.815 100.331,59.048 99.865,59.515 98.016,59.515 ; 96.845,60.183 97.348,60.183 98.016,59.515
  GND w0.5: v1(10.222,73.171) 10.218,73.167 v1(10.218,72.55) 10.218,72.261 v1(10.557,71.922)
  GND w0.55: v1@96.985,47.584 v1@98.287,47.584
  GND w0.7: P1.15@6.15,28.246 P1.6@8.15,30.246
  POWER w0.4: 36.824,55.081 38.728,56.986
  POWER w0.5: v1@10.218,73.167 v1(10.218,72.55) 10.218,72.261 v1(10.557,71.922)
  POWER w0.6: 26.587,47.61 27.023,47.175 32.237,47.175 32.668,47.606 ; 31.407,47.61 36.131,52.334 36.233,52.436 ; 53.533,40.608 54.596,40.608
  POWER w0.7: P1.15@6.15,28.246 P1.6@8.15,30.246
  POWER w1: P1.6@8.15,30.246 8.876,30.246 9.998,31.368 9.998,37.681 ; 15.194,42.606 18.977,42.606 19.922,43.551 19.922,43.822 ; 32.395,47.61 36.49,51.704 36.49,55.454 ; 36.971,55.936 38.021,56.986 ; 37.264,56.633 37.616,56.986 ; 41.493,56.862 JP1.1@42.229,56.126 ; JP1.1@42.128,56.986 38.728,56.986 38.021,56.986 ; JP1.1@42.581,55.429 42.996,55.843 42.996,56.888 42.26,57.624 38.254,57.624 37.616,56.986 ; 43.387,47.496 44.019,46.864 ; 43.387,51.463 43.435,51.511 42.23,52.715 42.23,56.773 42.392,56.935 42.551,56.776 42.551,53.306 44.019,51.838 44.019,46.864 ; 43.428,47.502 43.428,51.469 ; 44.11,47.593 51.145,40.558 ; 50.682,40.167 53.577,40.167 ; 51.002,40.202 50.682,40.202 50.325,40.558 ; 51.182,40.521 51.145,40.558 ; 61.749,40.279 62.308,40.279 65.766,36.821 76.608,36.821 ; 62.365,40.167 54.629,40.167 ; 65.397,37.89 66.089,37.198 66.238,37.198 65.984,37.452 ; 65.91,37.452 65.984,37.452 ; 76.355,37.452 77.239,37.452 ; 86.88,38.293 86.531,38.293 85.69,37.452 77.239,37.452 ; 87.414,38.176 86.059,36.821 76.608,36.821 ; 9.998,37.681 9.998,38.165 14.756,42.923 15.24,42.923 ; 9.998,37.681 10.165,37.848 10.165,37.879 10.722,38.436 10.753,38.436 15.24,42.923 ; 15.24,42.923 19.023,42.923 19.922,43.822 ; 19.922,43.822 19.922,46.513 21.019,47.61 26.587,47.61 31.407,47.61 32.111,47.61 36.131,51.63 36.131,52.334 36.131,55.504 37.612,56.986 37.616,56.986 ; 37.616,56.986 38.021,56.986 ; 44.019,46.864 50.325,40.558 ; 50.325,40.558 51.145,40.558 ; 51.145,40.558 53.186,40.558 53.577,40.167 ; 53.577,40.167 54.629,40.167 ; 54.629,40.167 55.02,40.558 62.878,40.558 65.984,37.452 ; 65.984,37.452 77.239,37.452 ; 76.608,36.821 77.239,37.452
  POWER w1.5: 86.88,38.293 86.909,38.321 96.866,38.321 98.175,39.63 98.175,47.408 97.51,48.073 v1@91.741,53.842
  Bottom Layer w0.45: U30.6@11.816,42.943 13.511,42.943 C84.1@13.732,42.722
  Bottom Layer w0.5: v1(10.222,73.171) CN13.50@11.101,73.171 ; v1@10.31,72.55 CN13.50@11.189,72.55 ; CN13.50@10.769,73.728 10.218,73.177 v1(10.218,72.55) 10.218,72.261 v1(10.557,71.922) CN13.50@11.178,72.544 ; U25.6@26.81,46.84 27.446,46.84 ; C58.1@28.406,46.242 28.044,46.242 27.446,46.84 ; C58.1@28.406,46.84 27.446,46.84 ; 29.137,47.54 28.146,47.54 ; C58.1@29.493,46.848 v1(29.493,47.838) v1(28.843,47.838) v1(28.146,47.838) 28.146,47.54 ; 27.446,46.84 28.146,47.54
  Bottom Layer w0.55: v1@96.985,47.584 v1@98.287,47.584
  Bottom Layer w0.7: P1.15@6.15,28.246 P1.6@8.15,30.246
  Bottom Layer w1: C84.1@13.742,42.928 C84.1@13.965,43.151
  Bottom Layer w1.2: C84.1@14.327,42.781 v1@15.253,42.781
  other v1: 14.899,42.423 15.471,42.816 14.891,43.151 96.985,47.549 98.285,47.574 91.074,53.874 91.774,53.875 91.074,54.535 91.774,54.535
5V_USB_CHG: C20.2 C32.1 CN9.1 D8.1 R39.2 R57.2 R63.2 R64.2 U13.5 U16.5 | length 94.2
  Top Layer w0.45: R39.2@73.111,46.928 v1(73.111,47.663) ; C20.2@84.778,70.561 84.104,69.887 84.104,69.35 84.21,69.244 84.452,69.244 84.83,69.621 CN9.1@84.83,71.84 ; R63.2@91.117,69.503 91.117,70.005 91.935,70.823 R64.2@93.984,70.823 R57.2@95.544,70.823 ; R63.2@91.223,68.704 v1(91.794,68.133) ; v1(92.418,68.123) 93.027,67.513 ; C32.1@92.491,67.436 v1(91.794,68.133) ; C32.1@92.552,67.056 U16.5@93.787,67.056 ; C32.1@92.552,67.234 93.027,67.234 ; C32.1@92.552,67.346 93.027,67.346 ; C32.1@92.785,67.479 92.726,67.538 92.131,68.133 ; 92.844,67.856 93.027,67.673 ; 93.027,67.137 93.027,67.234 ; v1(93.027,68.123) 93.027,67.673 ; v1@93.027,68.133 92.131,68.133 ; 93.039,67.502 93.027,67.513 ; U16.5@93.541,67.159 U16.5@93.467,67.234 ; U16.5@93.787,67.234 U16.5@93.467,67.234 ; U16.5@93.787,67.346 U16.5@93.355,67.346 ; v1(91.794,68.133) 92.131,68.133 ; 93.027,67.234 93.027,67.346 ; 93.027,67.234 U16.5@93.467,67.234 ; 93.027,67.346 U16.5@93.355,67.346 ; 93.027,67.346 93.027,67.513 ; 93.027,67.513 93.027,67.673 ; 93.027,67.673 U16.5@93.355,67.346 ; U16.5@93.355,67.346 U16.5@93.467,67.234
  Top Layer w0.5: U13.5@85.788,68.024 v1(85.788,68.917) ; D8.1@102.128,53.161 102.78,53.161 103.423,53.804 v1(103.423,53.9) ; D8.1@102.463,53.277 102.077,53.277 102.077,53.874 v1(102.103,53.9) v1@102.725,53.9 ; D8.1@102.763,53.277 v1(102.763,53.9) v1@103.386,53.9
  GND w0.55: v1(91.794,68.133) v1@93.027,68.133 ; v1@102.103,53.91 v1@103.423,53.91
  GND w0.8: v1@84.666,69.62 ccw(c84.416,69.62) v1@84.666,69.62
  POWER w0.3: 84.41,70.099 84.823,70.099 86.501,68.421
  POWER w0.5: 102.692,54.489 v1(102.103,53.9) v1(102.763,53.9) v1(103.423,53.9) 102.834,54.489
  POWER w1.2: 84.357,69.656 86.087,67.925 93.557,67.925 102.763,58.72 102.763,54.307
  Bottom Layer w0.45: v1(73.111,47.663) 74.118,48.671 74.118,59.115 v1(84.295,69.291)
  Bottom Layer w0.55: v1(91.794,68.133) v1@93.027,68.133 ; v1@102.103,53.91 v1@103.423,53.91
  Bottom Layer w0.8: v1@84.666,69.62 ccw(c84.416,69.62) v1@84.666,69.62
  other v1: 84.798,69.672 84.161,69.901
5V_USB_PWR: CN11.1 D11.1 D12.1 U21.1 | length 24.8
  Top Layer w0.45: 101.656,69.343 101.656,71.143 101.827,71.314 101.83,71.311 ; 101.683,70.685 101.83,70.539 ; U21.1@101.743,69.816 101.83,69.902 101.83,70.539 ; CN11.1@101.83,71.84 101.83,71.311 ; 101.999,69.343 101.999,70.37 ; 102.956,69.413 101.999,70.37 ; 101.83,70.539 101.83,71.311 ; 101.83,70.539 101.999,70.37 ; 101.83,71.311 101.999,71.143 101.999,70.37
  Top Layer w1: D11.1@102.441,55.369 D12.1@102.441,56.749
  Top Layer w1.5: 102.247,69.381 104.713,66.915 104.713,57.648 102.773,55.708
5V_USB_STLK: C26.2 D3.1 U16.1 | length 23.3
  Top Layer w0.8: U16.1@96.313,67.177 97.084,67.177 ; U16.1@96.37,67.145 96.916,66.6 ; 97.084,66.621 97.084,67.177 ; C26.2@97.856,67.177 97.084,67.177 ; 97.906,66.752 97.481,67.177 97.084,67.177
  Top Layer w1: 97.084,66.621 102.224,61.481 102.224,59.298 D3.1@102.441,59.082 ; 97.906,66.752 102.682,61.977 D3.1@102.682,59.082
AIN_1: R29.2 R55.2 R62.2 U12.10 | length 30.1
  Top Layer w0.3: v1(68.272,41.944) R29.2@68.272,42.637 ; v1(82.472,45.544) 82.472,48.739 82.752,49.018 84.41,49.018 85.23,49.838 U12.10@87.019,49.838 87.865,49.838 88.251,50.223 R55.2@88.251,52.673 89.203,53.625 R62.2@89.539,53.625
  POWER w0.3: v1(68.272,41.944) 69.886,43.558 71.675,43.558 72.816,44.699 v1(78.277,44.699)
  Bottom Layer w0.3: v1(78.277,44.699) 81.611,44.699 81.687,44.776 81.696,44.767 v1(82.472,45.544)
AVDD: C50.1 CN12.1 L1.1 TP17.1 U5.5 | length 54.5
  Top Layer w0.254: v1(56.059,38.419) 57.337,38.419 ; TP17.1@57.795,38.419 57.337,38.419 ; TP17.1@57.837,38.318 57.638,38.119 57.337,38.419
  Top Layer w0.4: U5.5@55.013,37.894 55.629,37.894 56.059,38.324 v1(56.059,38.419)
  Bottom Layer w0.5: v1(56.059,38.419) 55.426,38.419 L1.1@55.257,38.251 56.109,37.398 56.109,36.141 60.492,31.758 60.492,29.513 60.9,29.105 60.9,13.926 62.014,12.812 71.672,12.812 74.614,9.869 C50.1@74.614,5.894 72.337,3.616 CN12.1@72.337,3.005
eSIM_SWP: CN13.38 U5.81 | length 62.2
  Top Layer w0.2: U5.81@42.113,34.794 42.113,36.993 41.47,37.636 41.47,42.904 42.2,43.634 42.2,47.972 42.771,48.543 46.352,48.543 47.023,49.214 v1(47.042,49.214)
  POWER w0.2: v1(26.458,71.839) 26.458,67.398 27.37,66.486 30.181,66.486 ; 30.181,66.487 43.393,66.487 46.501,63.378 46.501,60.352 47.234,59.62 47.234,58.882 47.404,58.712 47.404,54.554 46.937,54.087 46.937,49.304 v1@47.03,49.211
  Bottom Layer w0.2: v1(26.458,71.839) 26.458,73.993 CN13.38@26.46,73.995
EXT_BAT: BT1.1 D4.1 D7.1 | length 16.2
  Top Layer w1.5: 93.771,55.47 95.346,55.47
  POWER w1.5: BT1.1@82.75,62.219 87.623,62.219 94.292,55.55 94.619,55.55
  other v1: 94.492,55.145 93.651,55.795 94.39,55.804 95.025,55.829
FFU_CLKOUT: CN13.17 SB47.1 U5.38 | length 53.7
  Top Layer w0.2: U5.38@48.713,51.794 48.713,54.233 v1(49.477,54.997)
  POWER w0.2: v1(22.346,55.594) 22.161,55.779 22.161,57.977 24.154,59.97 26.771,59.97 28.34,61.538 38.55,61.538 38.85,61.238 41.761,61.238 42.142,61.619 v1(42.142,63.191) ; v1(47.453,63.649) 47.301,63.497 47.301,60.684 48.034,59.951 48.034,59.425 49.477,57.981 v1(49.477,54.997)
  Bottom Layer w0.2: 22.346,55.21 v1(22.346,55.594) ; v1(42.142,63.191) 42.6,63.649 v1(47.453,63.649) 48.123,63.649 48.521,64.047 51.86,67.386 CN13.17@51.86,69.045 ; CN13.17@51.66,67.741 CN13.17@51.66,69.045
FFU_GNSS_COEX_IND: CN13.14 U5.21 | length 30.5
  Top Layer w0.2: U5.21@55.013,47.494 55.804,47.494 56.255,47.945 56.255,49.861 56.508,50.113 v1(56.508,50.387) ; v1(55.67,70.758) 58.719,67.709 58.719,62.729 58.718,62.727 58.718,62.272 58.719,62.27 58.719,60.998 v1(59.004,60.714)
  POWER w0.2: v1(56.508,50.387) 57.041,50.92 57.041,51.316 58.799,53.075 58.799,59.358 59.019,59.577 59.019,60.698 v1(59.004,60.714)
  Bottom Layer w0.2: v1(55.67,70.758) 55.67,71.52 56.94,72.79 CN13.14@56.94,73.995
FFU_GNSS_EXT_LNA: CN13.16 U5.22 | length 30.6
  Top Layer w0.2: v1(53.263,71.511) 53.263,70.675 53.257,70.669 58.319,65.607 58.319,62.895 58.318,62.893 58.318,62.106 58.319,62.104 58.319,61.007 58.318,61.005 58.318,59.957 v1(58.469,59.805) 58.469,59.685 58.462,59.678 v1@58.389,59.751 ; U5.22@55.013,48.094 55.678,48.094 55.855,48.271 55.855,50.696 v1(56.453,51.294)
  POWER w0.2: v1(56.453,51.294) 58.393,53.234 58.393,59.754 58.444,59.805 v1(58.469,59.805)
  Bottom Layer w0.2: v1(53.263,71.511) 54.4,72.648 CN13.16@54.4,73.995
FFU_GNSS_SFN_IND: CN13.18 U5.40 | length 30.2
  Top Layer w0.2: U5.40@47.513,51.794 47.513,52.422 47.404,52.531 47.404,57.035 47.778,57.408 49.064,57.408 49.872,58.217 50.886,58.217 52.644,59.975 53.351,59.975 53.894,60.518 53.894,65.507 52.275,67.126 v1(50.646,67.126)
  Bottom Layer w0.2: v1(50.646,67.126) 50.646,71.277 51.86,72.49 CN13.18@51.86,73.995 CN13.18@51.352,73.487
FFU_I2C0_SCL: CN13.1 R13.1 R91.1 U5.66 | length 85.6
  Top Layer w0.2: v1(18.967,47.995) 18.967,46.478 18.987,46.458 18.977,46.449 22.357,43.069 33.096,43.069 34.49,44.463 35.717,44.463 36.321,43.86 R13.1@36.595,43.86 ; R13.1@36.595,43.763 37.779,43.763 38.699,42.844 v1(38.699,42.882) 38.892,42.69 40.613,42.69 U5.66@40.613,42.694
  POWER w0.2: v1(52.77,45.249) 52.77,43.805 53.595,42.981 55.981,42.981 57.043,44.043 57.043,45.571 56.779,45.835 56.779,46.279 57.223,46.724 57.223,49.732 57.841,50.35 57.841,50.875 58.142,51.176 58.142,51.188 59.613,52.659 61.712,52.659 62.1,53.047 62.1,57.544 v1(62.128,57.572)
  Bottom Layer w0.2: R91.1@18.18,49.527 18.981,48.726 18.967,48.712 v1(18.967,47.995) ; v1(38.699,42.882) 38.892,42.69 40.035,42.69 40.038,42.694 40.999,42.694 43.387,45.082 43.387,45.363 43.944,45.919 44.876,45.919 45.542,45.919 45.758,45.703 45.785,45.703 45.787,45.702 51.999,45.702 52.442,45.259 v1@52.77,45.259 ; v1(62.128,57.572) 62.397,57.841 62.397,62.448 63.496,63.547 67.968,63.547 72.18,67.759 CN13.1@72.18,69.045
